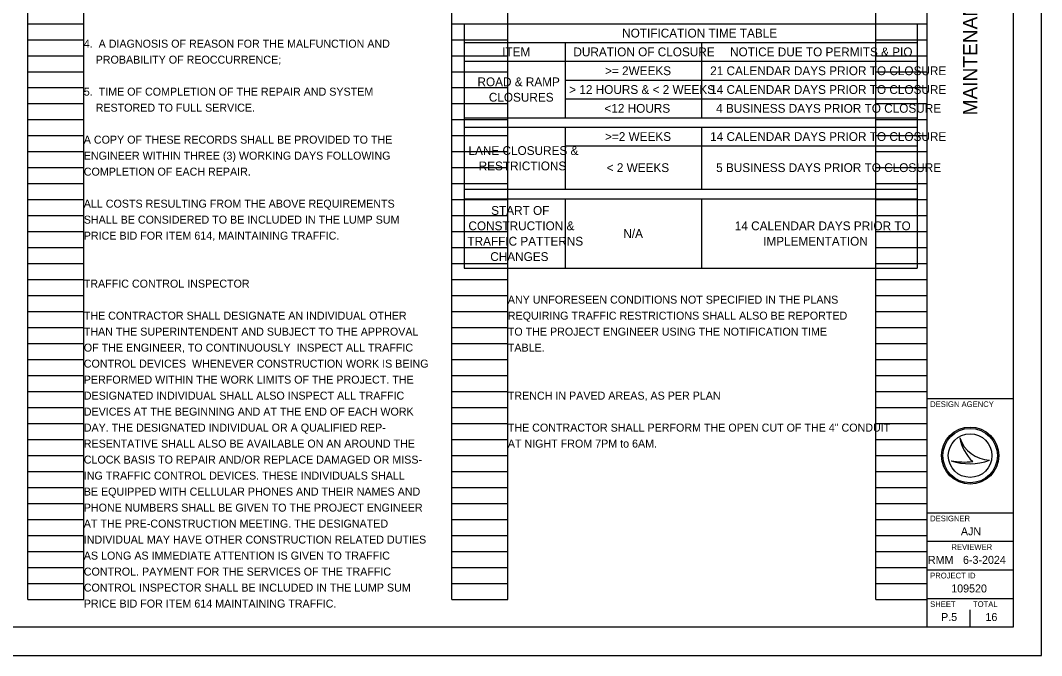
# Model space of a CAD drawing. Extents: x -7.3 to 34, y 0 to 22.
# Drawn here: x 16.13 to 34, y 0 to 11.12 of the extents above; entities that cross this region are included whole.
import ezdxf

# ---------------------------------------------------------------- set-up
doc = ezdxf.new("R2010")
doc.units = 0
for name, color, linetype in [('SH_Border', 7, 'Continuous'), ('SH_Cut_Line', 7, 'Continuous'), ('SH_Data', 7, 'Continuous'), ('SH_Text', 7, 'Continuous')]:
    doc.layers.add(name, color=color, linetype=linetype)

msp = doc.modelspace()

# ---------------------------------------------------------------- linework, layer by layer
at = {"layer": 'SH_Border'}
for p, q in [((32, 0.5), (32, 21.5)), ((32, 4.5), (33.5, 4.5)), ((32, 2.5), (33.5, 2.5)), ((32, 2), (33.5, 2)), ((32, 1.5), (33.5, 1.5)), ((32, 1), (33.5, 1))]:
    msp.add_line(p, q, dxfattribs=at)
msp.add_lwpolyline([(1.5, 21.5), (33.5, 21.5), (33.5, 0.5), (1.5, 0.5)], close=True, dxfattribs=at)
at = {"layer": 'SH_Cut_Line'}
msp.add_lwpolyline([(0, 0), (34, 0), (34, 22), (0, 22)], close=True, dxfattribs=at)
at = {"layer": 'SH_Data'}
for p, q in [((16.26, 0.98), (16.26, 21.14)), ((17.24, 0.98), (17.24, 21.14)), ((23.68, 0.98), (23.68, 21.14)), ((24.66, 0.98), (24.66, 21.14)), ((31.1, 0.98), (31.1, 21.14)), ((32, 0.98), (32, 21.14)), ((16.26, 11.06), (17.24, 11.06)), ((23.68, 11.06), (24.66, 11.06)), ((31.1, 11.06), (32, 11.06)), ((16.26, 10.78), (17.24, 10.78)), ((23.68, 10.78), (24.66, 10.78)), ((31.1, 10.78), (32, 10.78)), ((16.26, 10.5), (17.24, 10.5)), ((23.68, 10.5), (24.66, 10.5)), ((31.1, 10.5), (32, 10.5)), ((16.26, 10.22), (17.24, 10.22)), ((23.68, 10.22), (24.66, 10.22)), ((31.1, 10.22), (32, 10.22)), ((16.26, 9.94), (17.24, 9.94)), ((23.68, 9.94), (24.66, 9.94)), ((31.1, 9.94), (32, 9.94)), ((16.26, 9.66), (17.24, 9.66)), ((23.68, 9.66), (24.66, 9.66)), ((31.1, 9.66), (32, 9.66)), ((16.26, 9.38), (17.24, 9.38)), ((23.68, 9.38), (24.66, 9.38)), ((31.1, 9.38), (32, 9.38)), ((16.26, 9.1), (17.24, 9.1)), ((23.68, 9.1), (24.66, 9.1)), ((31.1, 9.1), (32, 9.1)), ((16.26, 8.82), (17.24, 8.82)), ((23.68, 8.82), (24.66, 8.82)), ((31.1, 8.82), (32, 8.82)), ((16.26, 8.54), (17.24, 8.54)), ((23.68, 8.54), (24.66, 8.54)), ((31.1, 8.54), (32, 8.54)), ((16.26, 8.26), (17.24, 8.26)), ((23.68, 8.26), (24.66, 8.26)), ((31.1, 8.26), (32, 8.26)), ((16.26, 7.98), (17.24, 7.98)), ((23.68, 7.98), (24.66, 7.98)), ((31.1, 7.98), (32, 7.98)), ((16.26, 7.7), (17.24, 7.7)), ((23.68, 7.7), (24.66, 7.7)), ((31.1, 7.7), (32, 7.7)), ((16.26, 7.42), (17.24, 7.42)), ((23.68, 7.42), (24.66, 7.42)), ((31.1, 7.42), (32, 7.42)), ((16.26, 7.14), (17.24, 7.14)), ((23.68, 7.14), (24.66, 7.14)), ((31.1, 7.14), (32, 7.14)), ((16.26, 6.86), (17.24, 6.86)), ((23.68, 6.86), (24.66, 6.86)), ((31.1, 6.86), (32, 6.86)), ((16.26, 6.58), (17.24, 6.58)), ((23.68, 6.58), (24.66, 6.58)), ((31.1, 6.58), (32, 6.58)), ((16.26, 6.3), (17.24, 6.3)), ((23.68, 6.3), (24.66, 6.3)), ((31.1, 6.3), (32, 6.3)), ((16.26, 6.02), (17.24, 6.02)), ((23.68, 6.02), (24.66, 6.02)), ((31.1, 6.02), (32, 6.02)), ((16.26, 5.74), (17.24, 5.74)), ((23.68, 5.74), (24.66, 5.74)), ((31.1, 5.74), (32, 5.74)), ((16.26, 5.46), (17.24, 5.46)), ((23.68, 5.46), (24.66, 5.46)), ((31.1, 5.46), (32, 5.46)), ((16.26, 5.18), (17.24, 5.18)), ((23.68, 5.18), (24.66, 5.18)), ((31.1, 5.18), (32, 5.18)), ((16.26, 4.9), (17.24, 4.9)), ((23.68, 4.9), (24.66, 4.9)), ((31.1, 4.9), (32, 4.9)), ((16.26, 4.62), (17.24, 4.62)), ((23.68, 4.62), (24.66, 4.62)), ((31.1, 4.62), (32, 4.62)), ((16.26, 4.34), (17.24, 4.34)), ((23.68, 4.34), (24.66, 4.34)), ((31.1, 4.34), (32, 4.34)), ((16.26, 4.06), (17.24, 4.06)), ((23.68, 4.06), (24.66, 4.06)), ((31.1, 4.06), (32, 4.06)), ((16.26, 3.78), (17.24, 3.78)), ((23.68, 3.78), (24.66, 3.78)), ((31.1, 3.78), (32, 3.78)), ((32.567, 3.81), (32.567, 3.81)), ((16.26, 3.5), (17.24, 3.5)), ((23.68, 3.5), (24.66, 3.5)), ((31.1, 3.5), (32, 3.5)), ((32.417, 3.41), (32.417, 3.41)), ((32.75, 3.5), (32.75, 3.5)), ((33.087, 3.419), (33.087, 3.419)), ((16.26, 3.22), (17.24, 3.22)), ((23.68, 3.22), (24.66, 3.22)), ((31.1, 3.22), (32, 3.22)), ((16.26, 2.94), (17.24, 2.94)), ((23.68, 2.94), (24.66, 2.94)), ((31.1, 2.94), (32, 2.94)), ((16.26, 2.66), (17.24, 2.66)), ((23.68, 2.66), (24.66, 2.66)), ((31.1, 2.66), (32, 2.66)), ((16.26, 2.38), (17.24, 2.38)), ((23.68, 2.38), (24.66, 2.38)), ((31.1, 2.38), (32, 2.38)), ((16.26, 2.1), (17.24, 2.1)), ((23.68, 2.1), (24.66, 2.1)), ((31.1, 2.1), (32, 2.1)), ((16.26, 1.82), (17.24, 1.82)), ((23.68, 1.82), (24.66, 1.82)), ((31.1, 1.82), (32, 1.82)), ((16.26, 1.54), (17.24, 1.54)), ((23.68, 1.54), (24.66, 1.54)), ((31.1, 1.54), (32, 1.54)), ((16.26, 1.26), (17.24, 1.26)), ((23.68, 1.26), (24.66, 1.26)), ((31.1, 1.26), (32, 1.26)), ((16.26, 0.98), (17.24, 0.98)), ((23.68, 0.98), (24.66, 0.98)), ((31.1, 0.98), (32, 0.98)), ((32.75, 0.5), (32.75, 0.8)), ((32.375, 0.675), (32.375, 0.675))]:
    msp.add_line(p, q, dxfattribs=at)
for radius in [0.5, 0.477, 0.477, 0.382]:
    msp.add_circle((32.75, 3.5), radius, dxfattribs=at)
for centre, radius, start, end in [((33.116, 3.998), 0.58, 198.9257, 198.9319), ((33.347, 3.97), 0.796, 191.6379, 191.6421), ((33.116, 3.998), 0.58, 198.9319, 267.1657), ((33.347, 3.97), 0.796, 191.6421, 226.0947), ((32.739, 4.37), 1.013, 251.4576, 290.0832), ((32.648, 4.654), 1.266, 259.4964, 259.4995), ((32.739, 4.37), 1.013, 251.4527, 251.4576), ((32.648, 4.654), 1.266, 259.4995, 276.6672)]:
    msp.add_arc(centre, radius, start, end, dxfattribs=at)
at = {"layer": 'SH_Text'}
for p, q in [((23.899, 11.06), (31.821, 11.06)), ((23.899, 11.06), (23.899, 6.778)), ((31.821, 11.06), (31.821, 6.778)), ((23.899, 10.731), (31.821, 10.731)), ((25.661, 10.731), (25.661, 9.413)), ((28.049, 10.731), (28.049, 9.413)), ((23.899, 10.401), (31.821, 10.401)), ((25.661, 10.072), (31.821, 10.072)), ((25.661, 9.742), (31.821, 9.742)), ((23.899, 9.413), (31.821, 9.413)), ((23.899, 9.248), (31.821, 9.248)), ((25.661, 9.248), (25.661, 8.161)), ((28.049, 9.248), (28.049, 8.161)), ((25.661, 8.919), (31.821, 8.919)), ((23.899, 8.161), (31.821, 8.161)), ((23.899, 7.996), (31.821, 7.996)), ((25.661, 7.996), (25.661, 6.778)), ((28.049, 7.996), (28.049, 6.778)), ((23.899, 6.778), (31.821, 6.778))]:
    msp.add_line(p, q, dxfattribs=at)

# ---------------------------------------------------------------- texts
at = {"layer": 'SH_Data'}
msp.add_text('MAINTENANCE OF TRAFFIC GENERAL NOTES', height=0.25, rotation=90, dxfattribs=at).set_placement((32.875, 9.455))
for s, height, p in [('DESIGN AGENCY', 0.1, (32.05, 4.35)), ('DESIGNER', 0.1, (32.05, 2.35)), ('AJN', 0.14, (32.588, 2.105)), ('REVIEWER', 0.1, (32.422, 1.85)), ('RMM', 0.14, (32.011, 1.605)), ('6-3-2024', 0.14, (32.625, 1.605)), ('PROJECT ID', 0.1, (32.05, 1.35)), ('109520', 0.14, (32.419, 1.105)), ('SHEET', 0.1, (32.05, 0.85)), ('TOTAL', 0.1, (32.8, 0.85)), ('P.5', 0.14, (32.241, 0.605)), ('16', 0.14, (33.018, 0.605))]:
    msp.add_text(s, height=height, dxfattribs=at).set_placement(p)
at = {"layer": 'SH_Text'}
for s, height, p in [('NOTIFICATION TIME TABLE', 0.154, (26.661, 10.818)), ('4.  A DIAGNOSIS OF REASON FOR THE MALFUNCTION AND', 0.14, (17.24, 10.64)), ('ITEM', 0.154, (24.562, 10.489)), ('DURATION OF CLOSURE', 0.154, (25.808, 10.489)), ('NOTICE DUE TO PERMITS & PIO', 0.154, (28.549, 10.489)), ('    PROBABILITY OF REOCCURRENCE;', 0.14, (17.24, 10.36)), ('>= 2WEEKS', 0.154, (26.361, 10.159)), ('21 CALENDAR DAYS PRIOR TO CLOSURE', 0.154, (28.201, 10.159)), ('ROAD & RAMP ', 0.154, (24.129, 9.965)), ('5.  TIME OF COMPLETION OF THE REPAIR AND SYSTEM', 0.14, (17.24, 9.8)), ('CLOSURES', 0.154, (24.328, 9.695)), ('> 12 HOURS & < 2 WEEKS', 0.154, (25.734, 9.83)), ('14 CALENDAR DAYS PRIOR TO CLOSURE', 0.154, (28.201, 9.83)), ('    RESTORED TO FULL SERVICE.', 0.14, (17.24, 9.52)), ('<12 HOURS', 0.154, (26.351, 9.501)), ('4 BUSINESS DAYS PRIOR TO CLOSURE', 0.154, (28.305, 9.501)), ('>=2 WEEKS', 0.154, (26.361, 9.007)), ('14 CALENDAR DAYS PRIOR TO CLOSURE', 0.154, (28.201, 9.007)), ('A COPY OF THESE RECORDS SHALL BE PROVIDED TO THE', 0.14, (17.24, 8.96)), ('ENGINEER WITHIN THREE (3) WORKING DAYS FOLLOWING', 0.14, (17.24, 8.68)), ('LANE CLOSURES & ', 0.154, (23.972, 8.762)), ('RESTRICTIONS', 0.154, (24.15, 8.493)), ('< 2 WEEKS', 0.154, (26.39, 8.463)), ('5 BUSINESS DAYS PRIOR TO CLOSURE', 0.154, (28.305, 8.463)), ('COMPLETION OF EACH REPAIR.', 0.14, (17.24, 8.4)), ('ALL COSTS RESULTING FROM THE ABOVE REQUIREMENTS', 0.14, (17.24, 7.84)), ('START OF ', 0.154, (24.369, 7.714)), ('SHALL BE CONSIDERED TO BE INCLUDED IN THE LUMP SUM', 0.14, (17.24, 7.56)), ('CONSTRUCTION & ', 0.154, (23.971, 7.445)), ('14 CALENDAR DAYS PRIOR TO ', 0.154, (28.632, 7.445)), ('PRICE BID FOR ITEM 614, MAINTAINING TRAFFIC.', 0.14, (17.24, 7.28)), ('TRAFFIC PATTERNS ', 0.154, (23.953, 7.175)), ('N/A', 0.154, (26.681, 7.31)), ('IMPLEMENTATION', 0.154, (29.128, 7.175)), ('CHANGES', 0.154, (24.353, 6.906)), ('TRAFFIC CONTROL INSPECTOR', 0.14, (17.24, 6.44)), ('ANY UNFORESEEN CONDITIONS NOT SPECIFIED IN THE PLANS', 0.14, (24.66, 6.16)), ('THE CONTRACTOR SHALL DESIGNATE AN INDIVIDUAL OTHER', 0.14, (17.24, 5.88)), ('REQUIRING TRAFFIC RESTRICTIONS SHALL ALSO BE REPORTED', 0.14, (24.66, 5.88)), ('THAN THE SUPERINTENDENT AND SUBJECT TO THE APPROVAL', 0.14, (17.24, 5.6)), ('TO THE PROJECT ENGINEER USING THE NOTIFICATION TIME', 0.14, (24.66, 5.6)), ('OF THE ENGINEER, TO CONTINUOUSLY  INSPECT ALL TRAFFIC', 0.14, (17.24, 5.32)), ('TABLE.', 0.14, (24.66, 5.32)), ('CONTROL DEVICES  WHENEVER CONSTRUCTION WORK IS BEING', 0.14, (17.24, 5.04)), ('PERFORMED WITHIN THE WORK LIMITS OF THE PROJECT. THE', 0.14, (17.24, 4.76)), ('DESIGNATED INDIVIDUAL SHALL ALSO INSPECT ALL TRAFFIC', 0.14, (17.24, 4.48)), ('TRENCH IN PAVED AREAS, AS PER PLAN', 0.14, (24.66, 4.48)), ('DEVICES AT THE BEGINNING AND AT THE END OF EACH WORK', 0.14, (17.24, 4.2)), ('DAY. THE DESIGNATED INDIVIDUAL OR A QUALIFIED REP-', 0.14, (17.24, 3.92)), ('THE CONTRACTOR SHALL PERFORM THE OPEN CUT OF THE 4" CONDUIT', 0.14, (24.66, 3.92)), ('RESENTATIVE SHALL ALSO BE AVAILABLE ON AN AROUND THE', 0.14, (17.24, 3.64)), ('AT NIGHT FROM 7PM to 6AM.', 0.14, (24.66, 3.64)), ('CLOCK BASIS TO REPAIR AND/OR REPLACE DAMAGED OR MISS-', 0.14, (17.24, 3.36)), ('ING TRAFFIC CONTROL DEVICES. THESE INDIVIDUALS SHALL', 0.14, (17.24, 3.08)), ('BE EQUIPPED WITH CELLULAR PHONES AND THEIR NAMES AND', 0.14, (17.24, 2.8)), ('PHONE NUMBERS SHALL BE GIVEN TO THE PROJECT ENGINEER', 0.14, (17.24, 2.52)), ('AT THE PRE-CONSTRUCTION MEETING. THE DESIGNATED', 0.14, (17.24, 2.24)), ('INDIVIDUAL MAY HAVE OTHER CONSTRUCTION RELATED DUTIES', 0.14, (17.24, 1.96)), ('AS LONG AS IMMEDIATE ATTENTION IS GIVEN TO TRAFFIC', 0.14, (17.24, 1.68)), ('CONTROL. PAYMENT FOR THE SERVICES OF THE TRAFFIC', 0.14, (17.24, 1.4)), ('CONTROL INSPECTOR SHALL BE INCLUDED IN THE LUMP SUM', 0.14, (17.24, 1.12)), ('PRICE BID FOR ITEM 614 MAINTAINING TRAFFIC.', 0.14, (17.24, 0.84))]:
    msp.add_text(s, height=height, dxfattribs=at).set_placement(p)

doc.saveas('drawing.dxf')
